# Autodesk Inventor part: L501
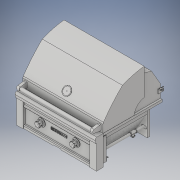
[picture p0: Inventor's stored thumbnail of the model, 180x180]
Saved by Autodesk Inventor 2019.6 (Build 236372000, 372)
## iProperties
Created: 2025-04
Part Number: L501
Material: Generic
Description: STEP AP203
Document SubType Name: Modeling
Designer: MMAK
Density: 1 g/cm^3
Appearance: Default
Sending System: SolidWorks 2024
Preprocessor: SwSTEP 2.0
Title: L501.STEP
Revision Number: ANY
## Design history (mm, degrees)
fillet "Boss-Extrude11"
fillet "Boss-Extrude16"
fillet "_31773-RM_-_Cut-Extrude3_"
fillet "_31773-RM_-_Cut-Extrude3_:1"
fillet "_34106_-_Dome1_"
fillet "Fillet9"
fillet "_13029_-_Extrude6_"
fillet "Cut-Extrude12"
fillet "Boss-Extrude33"
fillet "_33558_-_Fillet1_"
fillet "_34268_-_Fillet1_"
body "Solid1"
body "Solid2"
body "Solid3"
body "Solid4"
body "Solid5"
body "Solid6"
body "Solid7"
body "Solid8"
body "Solid9"
body "Solid10"
body "Solid11"
